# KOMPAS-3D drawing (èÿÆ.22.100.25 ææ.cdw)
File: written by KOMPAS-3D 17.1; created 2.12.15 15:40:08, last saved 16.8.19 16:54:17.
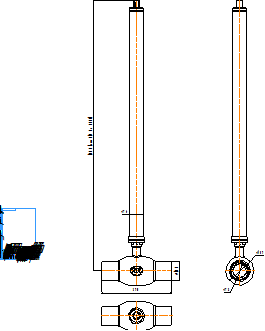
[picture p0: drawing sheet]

Sheet 1: A4, portrait

Title block, sheet 1: name: КШТ.22.100.25 С/С; sheets: 1; organisation: ООО "АДЛ Групп"; sheet format: A4; stored path: C:\Users\kka\KOMPAS_Work\Модели кранов для исследований\DN50\С удлинением\КШГ.32.050.40 СС ГЧ _ Шаровой кран БИВАЛ Ду50 Ру4 МПа редуцированный под приварку, с удлинением штока H=1100.cdw

Views: Вид 1, Проекционный вид 2, Проекционный вид 3
Referenced files in C:\Users\kka\KOMPAS_Work\Модели кранов для исследований\DN80\С удлинением\: КШТ.22.080.25 СС.a3d, КШГ.35.065.25 СС.a3d!КШГ.45.065.10 СС!Деталь (локальная).m3d
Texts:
  Klimkovich
  ADL
  (от 319 до 5000)
  Рама для чертежей
  Лит-Масса-Масштаб
  Материал-Предприятие
  Масштаб
  Изм.
  Лист
  № докум.
  Подп.
  Дата
  Лит.
  Разраб.
  Пров.
  Т.контр.
  Листов
  Внимание! Данный продукт является объектом авторского права ООО «Торговый Дом АДЛ».
  Запрещается изменение, копирование, распространение
  (в том числе путем копирования на другие сайты и ресурсы в Интернете)
  или любое иное использование информации и объектов без предварительного
  согласия правообладателя (ООО «Торговый Дом АДЛ»).
  Н.контр.
  Утв.
  ООО "Торговый дом АДЛ"
  Изменение
  Номер документа
  Подпись
  Обозначение документа
  Наименование изделия
  Масса изделия по ГОСТ 2.109-73
  Порядковый номер листа
  Общее количество листов в документе
  Характер работы, выполненной лицом, подписавшим документ
  Наименование или индекс предприятия, выпускающего документ
  Инв. № подл.
  Подп. и дата
  Взам. инв. №
  Инв. № дубл.
  Инвентарный номер подлинника по ГОСТ 2.501-68
  Подпись принявшего подлинник в отдел технической документации
  Инвентарный номер подлинника, взамен которого выпущен данный подлинник
  Инвентарный номер дубликата по ГОСТ 2.502-68
  Подпись принявшего дубликат в отдел технической документации
  Справ. №
  Перв. примен.
  Обозначение документа, взамен или на основании которого выпущен данный документ
  Обозначение документа, в котором впервые записан данный документ
  Подпись лица, копировавшего чертеж
  Обозначение формата листа
  !Рама для чертежа
Dimensions and other numbers on the sheet: 1500; 76; 108; 390; 78; 159; 1:1; 1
